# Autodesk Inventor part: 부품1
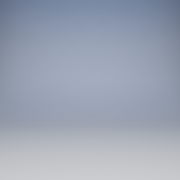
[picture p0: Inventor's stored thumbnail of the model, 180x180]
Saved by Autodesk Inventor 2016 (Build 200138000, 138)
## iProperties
Created: 2017-04
Part Number: 부품1
Material: 일반
Document SubType Name: Modeling
Designer: USER
Density: 1 g/cm^3
Appearance: 기본값
Author: USER
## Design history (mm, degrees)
